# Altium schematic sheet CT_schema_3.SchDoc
size 298 x 230 mm
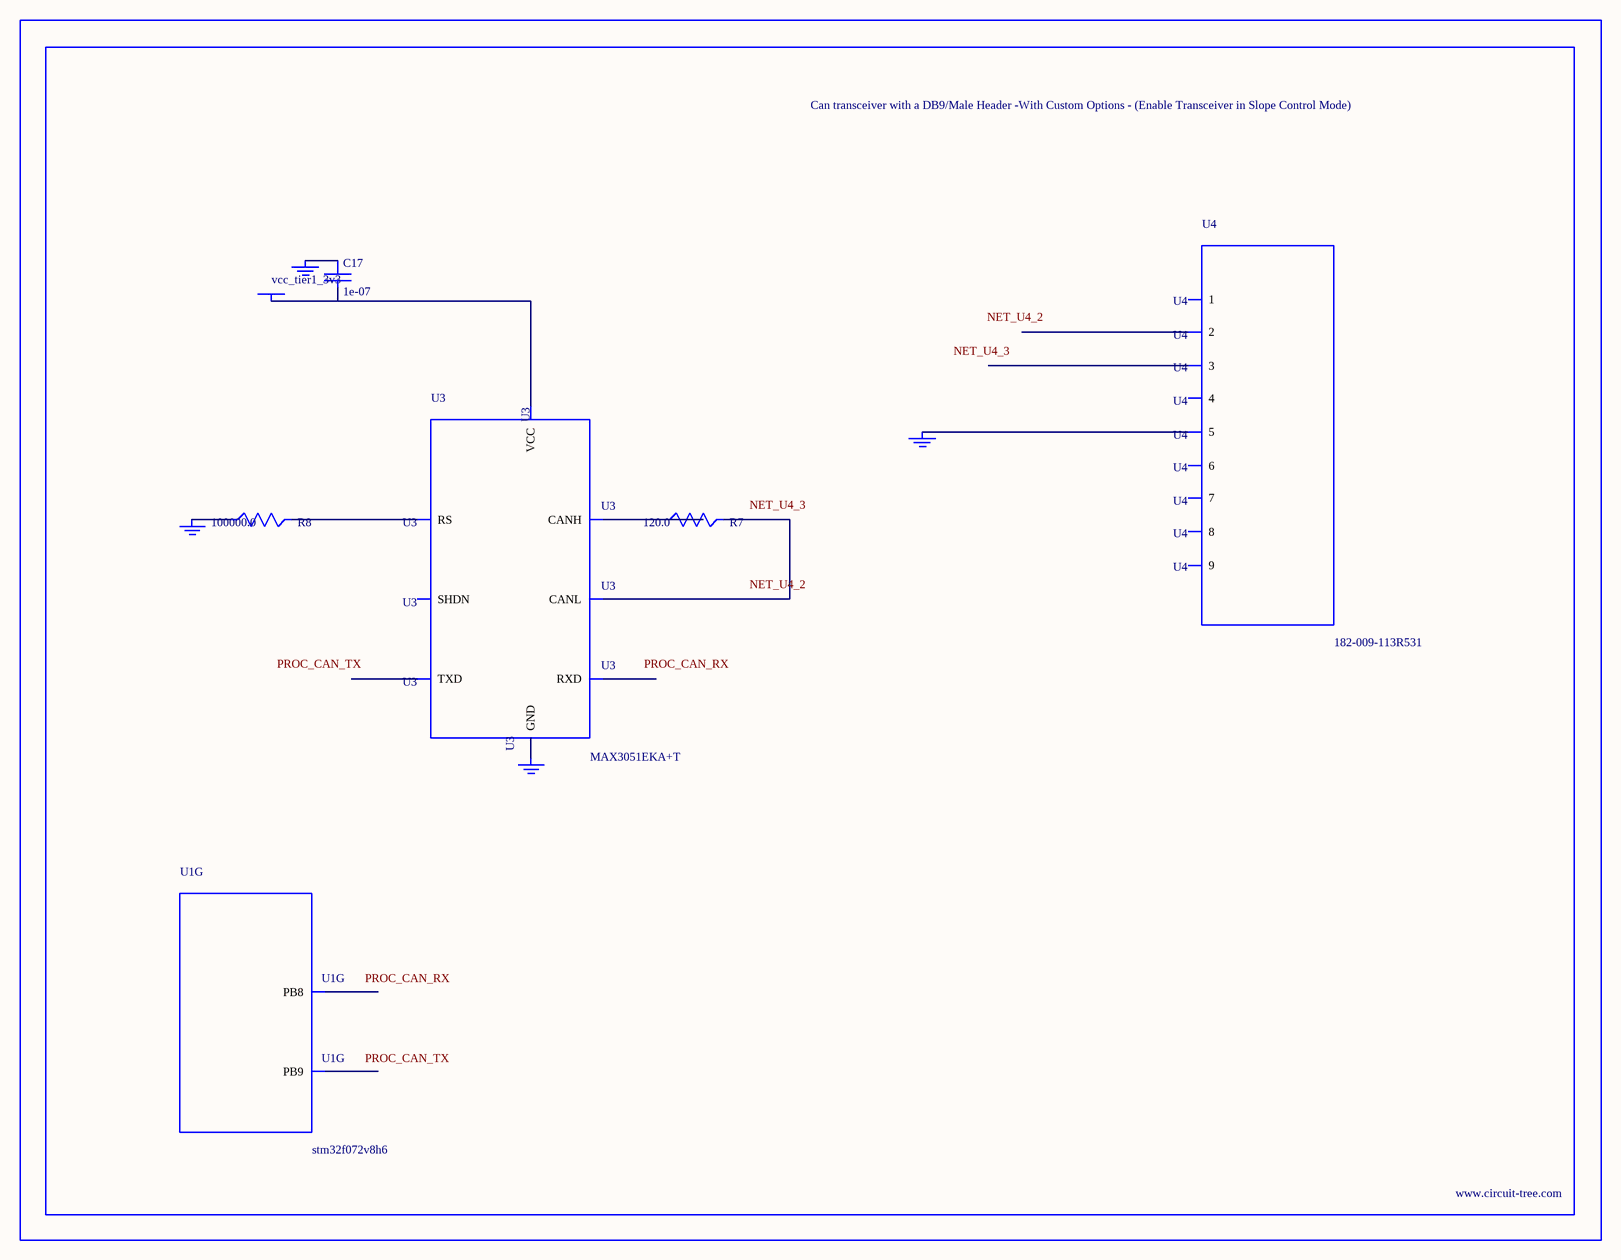
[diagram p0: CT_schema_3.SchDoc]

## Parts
BORDER2  (no value)
C17  1e-07  [C0402]
GND_INSTANCE_2_0  (no value)
GND_INSTANCE_2_1  (no value)
GND_INSTANCE_2_2  (no value)
GND_INSTANCE_2_3  (no value)
POWER_INSTANCE_2_0  vcc_tier1_3v3
R7  120.0  [R0603]
R8  100000.0  [R0603]
U1  stm32f072v8h6  [UFBGA100]  (part G of 10)
U3  MAX3051EKA+T  [SOT-23-8]
U4  182-009-113R531  [182-009-MALE]

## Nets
NetC17_1: C17.1 GND_INSTANCE_2_0.0(GND)
NetC17_2: C17.2 POWER_INSTANCE_2_0.0(PWR) U3.3(VCC)
NetGND_INSTANCE_2_1_0: GND_INSTANCE_2_1.0(GND) R8.1
NetGND_INSTANCE_2_2_0: GND_INSTANCE_2_2.0(GND) U3.2(GND)
NetGND_INSTANCE_2_3_0: GND_INSTANCE_2_3.0(GND) U4.5
NetR7_1: R7.1 U3.7(CANH)
NetR7_2: R7.2 U3.6(CANL)
NetR8_2: R8.2 U3.8(RS)

Not connected (* = marked no-connect by the designer): U1 A3(PB8) B3(PB9); U3 1(TXD) 4(RXD) 5(SHDN); U4 1 2 3 4 6 7 8 9

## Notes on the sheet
- Labels drawn without touching a wire or pin: NET_U4_2, NET_U4_3, PROC_CAN_RX, PROC_CAN_TX

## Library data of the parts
BORDER2 = BORDER_PAGE2
C17 = C0402C104K3RACTU
GND_INSTANCE_2_0-GND_INSTANCE_2_3 = GND
POWER_INSTANCE_2_0 = PWR
R7 = RC0603JR-07120RL
R8 = RC0603JR-07100KL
